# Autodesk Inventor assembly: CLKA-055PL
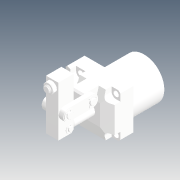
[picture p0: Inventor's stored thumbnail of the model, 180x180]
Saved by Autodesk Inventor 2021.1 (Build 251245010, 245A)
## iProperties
Created: 2019-04
Part Number: CLKA-055PL
Description: STEP AP214
Document SubType Name: Assembly
Designer: user
Title: CLKA-055PL.STEP
Revision Number: ÈÎºÎ
Sending System: SolidWorks 2016
Preprocessor: SwSTEP 2.0
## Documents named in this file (12)
- D:\Vault_2016\Projekty\Clamptek\Hydraulic\CLKA-P\Inventor\CLKA-055PL\CLKA-055PL.iam
- D:\Vault_2016\Projekty\Clamptek\Hydraulic\CLKA-P\Inventor\CLKA-055PL\CLKA-055P-L-benti.ipt
- D:\Vault_2016\Projekty\Clamptek\Hydraulic\CLKA-P\Inventor\CLKA-055PL\6MM¿ª¿Úµ²È¦.ipt
- D:\Vault_2016\Projekty\Clamptek\Hydraulic\CLKA-P\Inventor\CLKA-055PL\8MMdangjuan.ipt
- D:\Vault_2016\Projekty\Clamptek\Hydraulic\CLKA-P\Inventor\CLKA-055PL\duanxiao.ipt
- D:\Vault_2016\Projekty\Clamptek\Hydraulic\CLKA-P\Inventor\CLKA-055PL\huosaigan.ipt
- D:\Vault_2016\Projekty\Clamptek\Hydraulic\CLKA-P\Inventor\CLKA-055PL\liangan.ipt
- D:\Vault_2016\Projekty\Clamptek\Hydraulic\CLKA-P\Inventor\CLKA-055PL\luosi.ipt
- D:\Vault_2016\Projekty\Clamptek\Hydraulic\CLKA-P\Inventor\CLKA-055PL\M8luomu.ipt
- D:\Vault_2016\Projekty\Clamptek\Hydraulic\CLKA-P\Inventor\CLKA-055PL\yabi.ipt
- D:\Vault_2016\Projekty\Clamptek\Hydraulic\CLKA-P\Inventor\CLKA-055PL\zhangxiao.ipt
- D:\Vault_2016\Projekty\Clamptek\Hydraulic\CLKA-P\Inventor\CLKA-055PL\¶ÂÍ·G8-1.ipt
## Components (18 placed, 18 different names)
1. CLKA-055P-L-benti_1
2. 6MM¿ª¿Úµ²È¦_2
3. 8MMdangjuan_3
4. duanxiao_4
5. huosaigan_5
6. liangan_6
7. luosi_7
8. M8luomu_8
9. yabi_9
10. zhangxiao_10
11. liangan_11
12. zhangxiao_12
13. 6MM¿ª¿Úµ²È¦_13
14. 8MMdangjuan_14
15. 8MMdangjuan_15
16. 8MMdangjuan_16
17. ¶ÂÍ·G8-1_17
18. ¶ÂÍ·G8-1_18
